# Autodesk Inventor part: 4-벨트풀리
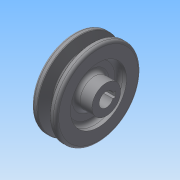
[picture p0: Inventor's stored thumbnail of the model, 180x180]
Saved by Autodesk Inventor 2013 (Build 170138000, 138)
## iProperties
Created: 2015-02
Part Number: 4-벨트풀리
Material: 일반
Document SubType Name: Modeling
Designer: Administrator
Density: 1 g/cm^3
Author: Administrator
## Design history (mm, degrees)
sketch "스케치1"
  geometry: L1 (0, 0)-(25, 0); L2 (0, 5.5)-(25, 5.5); L3 (0, 5.5)-(0, 11); L4 (0, 11)-(6, 11); L5 (6, 11)-(6, 21.5); L6 (6, 21.5)-(0, 21.5); L7 (0, 21.5)-(0, 32.5); L8 (0, 32.5)-(4.675, 32.5); L9 (4.675, 32.5)-(7.426, 23.5); L10 (7.426, 23.5)-(11.574, 23.5); L11 (11.574, 23.5)-(14.325, 32.5); L12 (14.325, 32.5)-(19, 32.5); L13 (19, 32.5)-(19, 21.5); L14 (19, 21.5)-(13, 21.5); L15 (13, 21.5)-(13, 11); L16 (13, 11)-(25, 11); L17 (25, 11)-(25, 5.5); 2 further points
  constraints: 34 end point, 10 parallel, 5 collinear, 3 vertical alignment, 2 equal length, 2 perpendicular, 2 point on line, 1 horizontal, 1 horizontal alignment
  dimensions: "d0" = 25 distance of L1.start L1.end; "d1" = 2.7 distance from line of point (5.5, 29.8) L8; "d2" = 6.3 distance from line of L10 point (5.5, 29.8); "d3" = 8 distance of point (13.5, 29.8) point (5.5, 29.8); "d4" = 34 deg angle of L11 L9; "d5" = 19 distance between parallel lines of L13 L7; "d6" = 6 distance of L5.end L6.end; "d7" = 6 distance of L13.end L14.end; "d8" = 11 diameter of L2 L1; "d9" = 22 diameter of L16 L1; "d10" = 43 diameter of L14 L1; "d11" = 65 diameter of L12 L1
revolve "회전1" sketch "스케치1" stored, may be unused: angle "d12" = 90 deg
fillet "모깎기1" dims "d13" = 2, "d14" = 0.5, "d15" = 1
sketch "스케치2"
  geometry: L1 (-2, 5.123)-(-2, 7.3); L2 (-2, 7.3)-(2, 7.3); L3 (2, 7.3)-(2, 5.123); A1 r 5.5 centre (0, 0) between (-2, 5.123) and (2, 5.123) reference
  constraints: 6 end point, 2 parallel, 2 point on circle, 1 perpendicular, 1 vertical
  dimensions: "d16" = 4 distance of L1.end L2.end; "d18" = 12.8 dimension on A1 L2
extrude "돌출1" cut sketch "스케치2" stored distance "d19" = 0; taper "d20" = 0 deg
fillet "모깎기2" dims "d21" = 3
fillet "모깎기3" dims "d22" = 3
node "솔리드1"
